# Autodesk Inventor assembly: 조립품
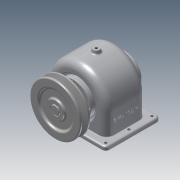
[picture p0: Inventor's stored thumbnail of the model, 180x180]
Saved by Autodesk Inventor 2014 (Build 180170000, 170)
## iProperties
Created: 2015-09
Part Number: 조립품
Document SubType Name: Assembly
Designer: sda3
Author: sda3
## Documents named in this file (14)
- C:\Users\sda3\Desktop\450907V1035\답안조립품.iam
- C:\Users\sda3\Desktop\450907V1035\본체.ipt
- C:\Users\sda3\Desktop\450907V1035\V-벨트풀리.ipt
- C:\Users\sda3\Desktop\450907V1035\뒤커버.ipt
- C:\Users\sda3\Desktop\450907V1035\멈춤나사 - M4x10.ipt
- C:\Users\sda3\Desktop\450907V1035\볼트 M3 x 8.ipt
- C:\Users\sda3\Desktop\450907V1035\볼트 M3 x 10.ipt
- C:\Users\sda3\Desktop\450907V1035\스퍼기어.ipt
- C:\Users\sda3\Desktop\450907V1035\앞커버.ipt
- C:\Users\sda3\Desktop\450907V1035\오일 실 17 32 8.ipt
- C:\Users\sda3\Desktop\450907V1035\축.ipt
- C:\Users\sda3\Desktop\450907V1035\키 - 5 x 5 x 18.ipt
- C:\Users\sda3\Desktop\450907V1035\키 - 6 x 6 x 22.ipt
- C:\Users\sda3\Desktop\450907V1035\베어링 6203.ipt
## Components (3 placed, 3 different names)
1. V-벨트풀리:1
2. ISO 4762 M3 x 8:1 — 각도:1
3. ISO 4762 M3 x 10:1 — 각도:2
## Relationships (2: Angle 2)
- 각도:1 [Angle]: ISO 4762 M3 x 8:1
- 각도:2 [Angle]: ISO 4762 M3 x 10:1
